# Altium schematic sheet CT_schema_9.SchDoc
size 281 x 153 mm
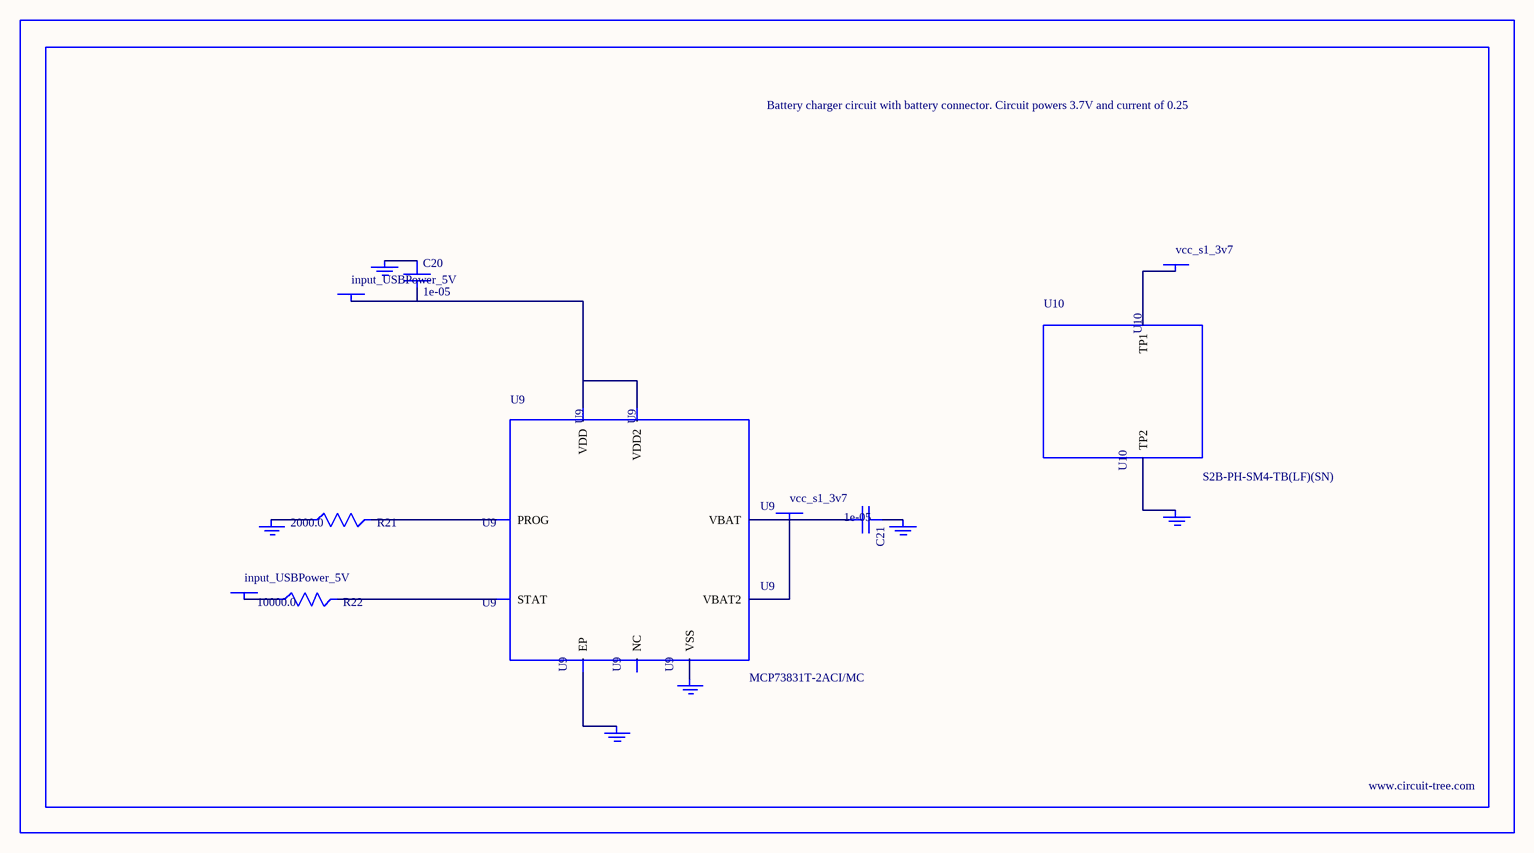
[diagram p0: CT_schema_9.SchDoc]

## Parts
BORDER8  (no value)
C20  1e-05  [C1206]
C21  1e-05  [C1206]
GND_INSTANCE_8_0  (no value)
GND_INSTANCE_8_1  (no value)
GND_INSTANCE_8_2  (no value)
GND_INSTANCE_8_3  (no value)
GND_INSTANCE_8_4  (no value)
GND_INSTANCE_8_5  (no value)
POWER_INSTANCE_8_0  input_USBPower_5V
POWER_INSTANCE_8_1  input_USBPower_5V
POWER_INSTANCE_8_2  vcc_s1_3v7
POWER_INSTANCE_8_3  vcc_s1_3v7
R21  2000.0  [R0603]
R22  10000.0  [R0603]
U9  MCP73831T-2ACI/MC  [DFN8_2X3MC]
U10  S2B-PH-SM4-TB(LF)(SN)  [JST-2-SMD]

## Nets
NetC20_1: C20.1 GND_INSTANCE_8_0.0(GND)
NetC20_2: C20.2 POWER_INSTANCE_8_0.0(PWR) U9.1(VDD) U9.2(VDD2)
NetC21_1: C21.1 GND_INSTANCE_8_1.0(GND)
NetC21_2: C21.2 POWER_INSTANCE_8_2.0(PWR) U9.3(VBAT) U9.4(VBAT2)
NetGND_INSTANCE_8_2_0: GND_INSTANCE_8_2.0(GND) R21.1
NetGND_INSTANCE_8_3_0: GND_INSTANCE_8_3.0(GND) U9.9(EP)
NetGND_INSTANCE_8_4_0: GND_INSTANCE_8_4.0(GND) U9.6(VSS)
NetGND_INSTANCE_8_5_0: GND_INSTANCE_8_5.0(GND) U10.2(TP2)
NetPOWER_INSTANCE_8_1_0: POWER_INSTANCE_8_1.0(PWR) R22.1
NetPOWER_INSTANCE_8_3_0: POWER_INSTANCE_8_3.0(PWR) U10.1(TP1)
NetR21_2: R21.2 U9.8(PROG)
NetR22_2: R22.2 U9.5(STAT)

Not connected (* = marked no-connect by the designer): U9 7(NC)

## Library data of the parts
BORDER8 = BORDER_PAGE8
C20 C21 = C1206C106K3RACTU
GND_INSTANCE_8_0-GND_INSTANCE_8_5 = GND
POWER_INSTANCE_8_0-POWER_INSTANCE_8_3 = PWR
R21 = RC0603JR-072KL
R22 = RC0603JR-0710KL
